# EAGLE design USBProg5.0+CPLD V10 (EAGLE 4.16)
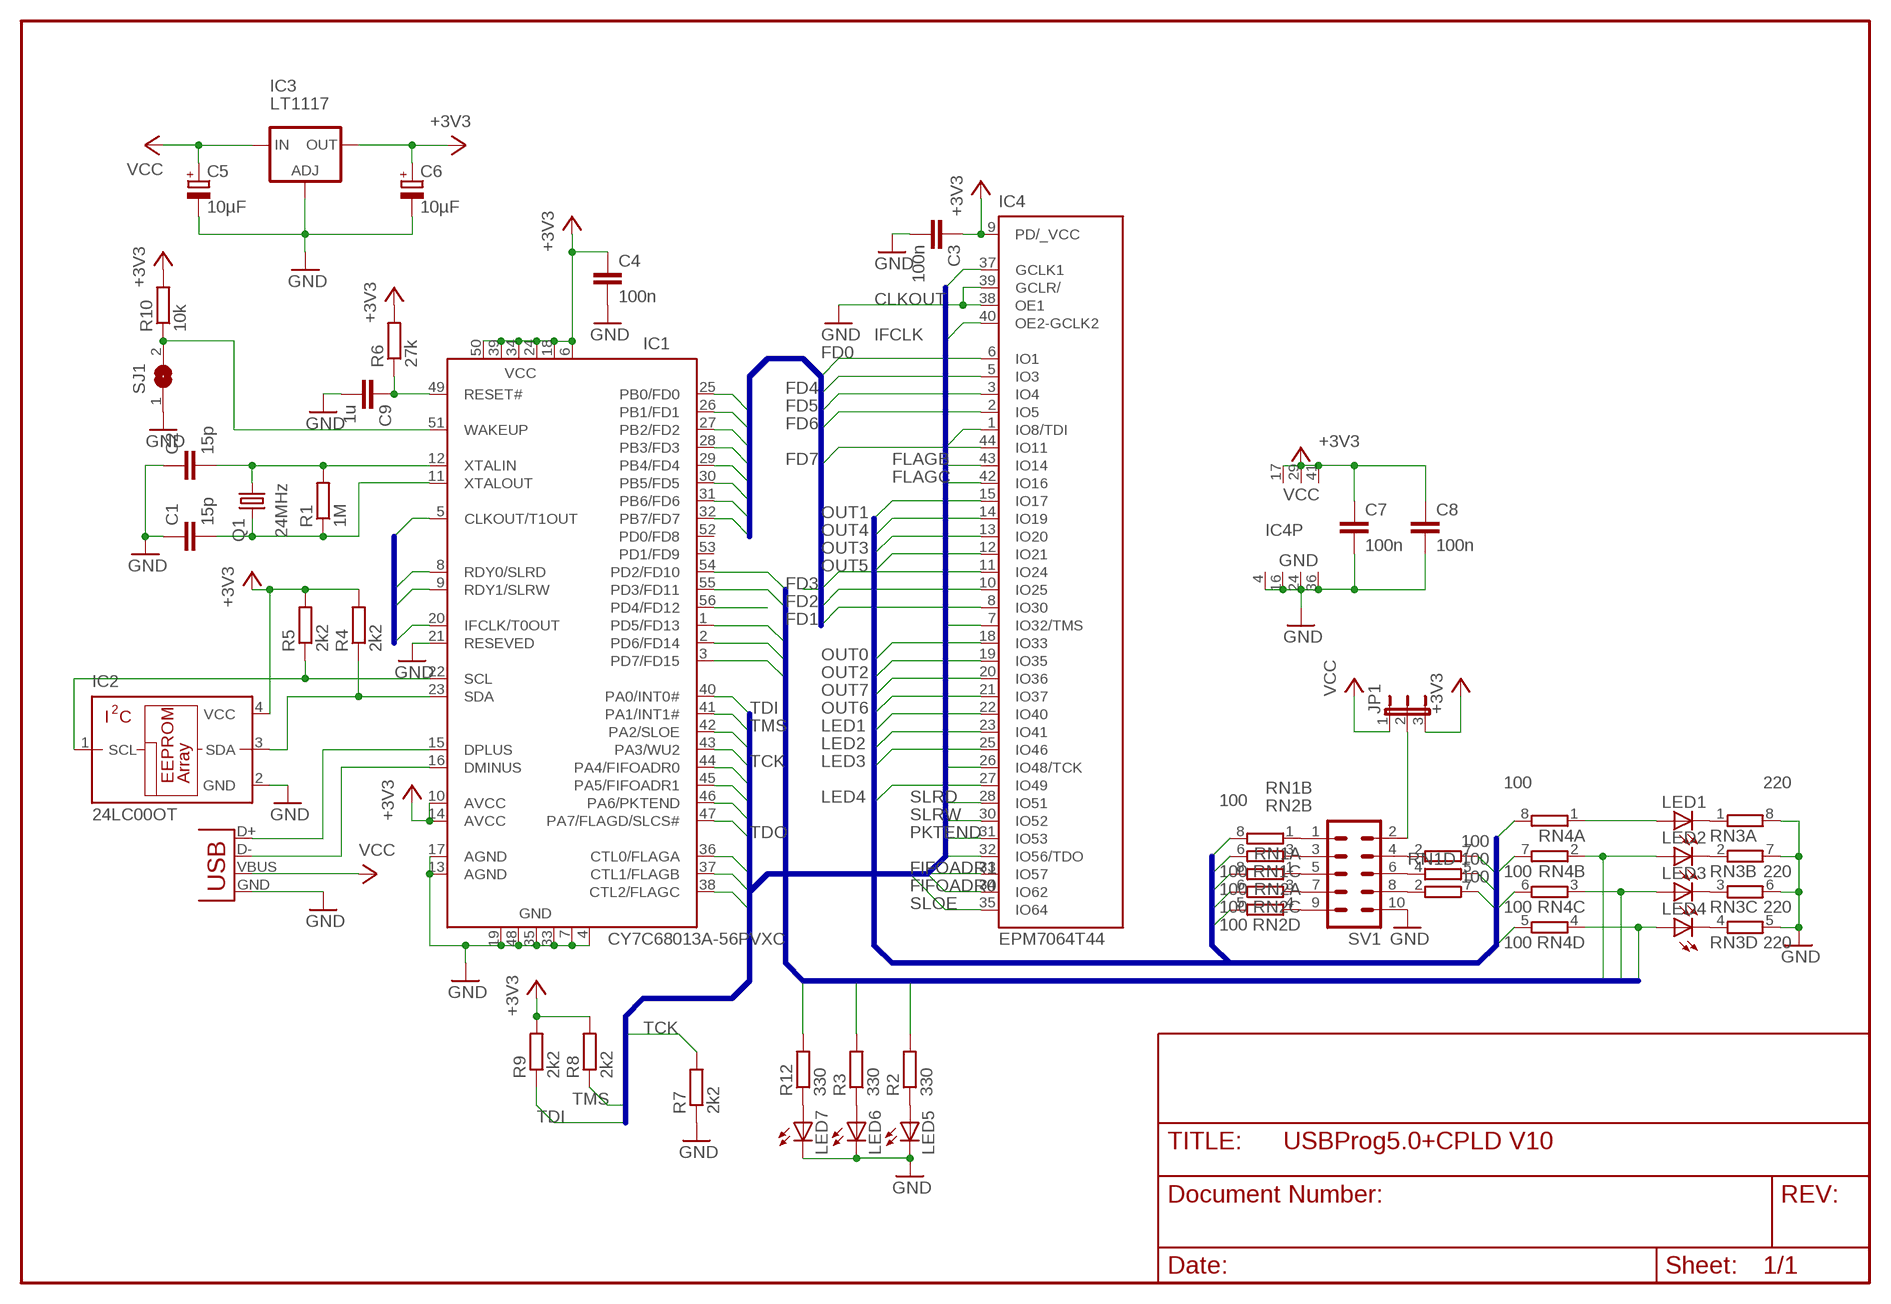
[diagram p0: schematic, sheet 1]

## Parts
C1  15p  RCL_C-EUC0603  [RCL_C0603]
C2  15p  RCL_C-EUC0603  [RCL_C0603]
C3  100n  RCL_C-EUC0603  [RCL_C0603]
C4  100n  RCL_C-EUC0603  [RCL_C0603]
C5  10µF  CPOL-EUSMCB  [SMC_B]
C6  10µF  CPOL-EUSMCB  [SMC_B]
C7  100n  RCL_C-EUC0603  [RCL_C0603]
C8  100n  RCL_C-EUC0603  [RCL_C0603]
C9  1u  RCL_C-EUC0805  [RCL_C0805]
IC1  CY7C68013A-56PVXC  [SSOP56]
IC2  24LC00OT  [SOT23-5L]
IC3  LT1117  LM317MBSTT3  [SOT223]
IC4  EPM7064T44  [TQFP44]
JP1  JP2E  [JP2]
LED1  LED_LEDCHIPLED_0603  [LED_CHIPLED_0603]
LED2  LED_LEDCHIPLED_0603  [LED_CHIPLED_0603]
LED3  LED_LEDCHIPLED_0603  [LED_CHIPLED_0603]
LED4  LED_LEDCHIPLED_0603  [LED_CHIPLED_0603]
LED5  LED_LEDCHIPLED_0603  [LED_CHIPLED_0603]
LED6  LED_LEDCHIPLED_0603  [LED_CHIPLED_0603]
LED7  LED_LEDCHIPLED_0603  [LED_CHIPLED_0603]
Q1  24MHz  CRYSTALSM49  [SM49]
R1  1M  RCL_R-EU_R0603  [RCL_R0603]
R2  330  RCL_R-EU_R0603  [RCL_R0603]
R3  330  RCL_R-EU_R0603  [RCL_R0603]
R4  2k2  RCL_R-EU_R0603  [RCL_R0603]
R5  2k2  RCL_R-EU_R0603  [RCL_R0603]
R6  27k  RCL_R-EU_R0603  [RCL_R0603]
R7  2k2  RCL_R-EU_R0603  [RCL_R0603]
R8  2k2  RCL_R-EU_R0603  [RCL_R0603]
R9  2k2  RCL_R-EU_R0603  [RCL_R0603]
R10  10k  RCL_R-EU_R0603  [RCL_R0603]
R12  330  RCL_R-EU_R0603  [RCL_R0603]
RN1  100  4R-N0402-ARV  [0402-ARV]
RN2  100  4R-N0402-ARV  [0402-ARV]
RN3  220  4R-N0402-ARV  [0402-ARV]
RN4  100  4R-N0402-ARV  [0402-ARV]
SJ1  SJ  [SJ]
SV1  ML10L  [ML10L]
X1  CON-USB_USB-B-H  [CON-USB_USB-B-H]

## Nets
+3V3: C3.1 C4.1 C6.+ C7.1 C8.1 IC1.6(VCC) IC1.10(AVCC) IC1.14(AVCC) IC1.18(VCC) IC1.24(VCC) IC1.34(VCC) IC1.39(VCC) IC1.50(VCC) IC2.4(VCC) IC3.4(OUT) IC4.9(PD/_VCC) IC4.17(VCC) IC4.29(VCC) IC4.41(VCC) JP1.3 R4.2 R5.2 R6.2 R8.2 R9.2 R10.2
CLKOUT: IC1.5(CLKOUT/T1OUT) IC4.37(GCLK1)
CPLD_LED1: LED1.A RN4.1
CPLD_LED2: IC1.55(PD3/FD11) LED2.A RN4.2
CPLD_LED3: IC1.56(PD4/FD12) LED3.A RN4.3
CPLD_LED4: IC1.54(PD2/FD10) LED4.A RN4.4
DMINUS: IC1.16(DMINUS) X1.D-
DPLUS: IC1.15(DPLUS) X1.D+
FD0: IC1.25(PB0/FD0) IC4.6(IO1)
FD1: IC1.26(PB1/FD1) IC4.8(IO30)
FD2: IC1.27(PB2/FD2) IC4.10(IO25)
FD3: IC1.28(PB3/FD3) IC4.11(IO24)
FD4: IC1.29(PB4/FD4) IC4.5(IO3)
FD5: IC1.30(PB5/FD5) IC4.3(IO4)
FD6: IC1.31(PB6/FD6) IC4.2(IO5)
FD7: IC1.32(PB7/FD7) IC4.44(IO11)
FIFOADR0: IC1.44(PA4/FIFOADR0) IC4.34(IO62)
FIFOADR1: IC1.45(PA5/FIFOADR1) IC4.33(IO57)
FLAGA: IC1.36(CTL0/FLAGA)
FLAGB: IC1.37(CTL1/FLAGB) IC4.43(IO14)
FLAGC: IC1.38(CTL2/FLAGC) IC4.42(IO16)
GND: C1.1 C2.1 C3.2 C4.2 C5.- C6.- C7.2 C8.2 C9.2 IC1.4(GND) IC1.7(GND) IC1.13(AGND) IC1.17(AGND) IC1.19(GND) IC1.21(RESEVED) IC1.33(GND) IC1.35(GND) IC1.48(GND) IC2.2(GND) IC3.1(ADJ) IC4.4(GND) IC4.16(GND) IC4.24(GND) IC4.36(GND) IC4.38(OE1) IC4.39(GCLR/) LED5.C LED6.C LED7.C R7.1 RN3.5 RN3.6 RN3.7 RN3.8 SJ1.1 SV1.10 X1.GND
IFCLK: IC1.20(IFCLK/T0OUT) IC4.40(OE2-GCLK2)
LED1: IC4.22(IO40) RN4.8
LED2: IC4.23(IO41) RN4.7
LED3: IC4.25(IO46) RN4.6
LED4: IC4.27(IO49) RN4.5
LED5: IC1.1(PD5/FD13) R2.2
LED6: IC1.2(PD6/FD14) R3.2
LED7: IC1.3(PD7/FD15) R12.2
N$1: C9.1 IC1.49(RESET#) R6.1
N$4: RN1.1 SV1.1
N$5: RN1.2 SV1.4
N$6: RN1.3 SV1.3
N$7: LED6.A R3.1
N$8: LED5.A R2.1
N$9: RN1.4 SV1.6
N$10: RN2.1 SV1.5
N$11: RN2.2 SV1.8
N$12: RN2.3 SV1.7
N$13: RN2.4 SV1.9
N$14: LED1.C RN3.1
N$15: LED2.C RN3.2
N$16: LED3.C RN3.3
N$17: LED4.C RN3.4
N$18: LED7.A R12.1
N$20: JP1.2 SV1.2
OUT0: IC4.18(IO33) RN2.8
OUT1: IC4.15(IO17) RN1.5
OUT2: IC4.19(IO35) RN2.7
OUT3: IC4.13(IO20) RN1.7
OUT4: IC4.14(IO19) RN1.6
OUT5: IC4.12(IO21) RN1.8
OUT6: IC4.21(IO37) RN2.5
OUT7: IC4.20(IO36) RN2.6
PKTEND: IC1.46(PA6/PKTEND) IC4.31(IO53)
SCL: IC1.22(SCL) IC2.1(SCL) R5.1
SDA: IC1.23(SDA) IC2.3(SDA) R4.1
SLOE: IC1.42(PA2/SLOE) IC4.35(IO64)
SLRD: IC1.8(RDY0/SLRD) IC4.28(IO51)
SLRW: IC1.9(RDY1/SLRW) IC4.30(IO52)
TCK: IC1.43(PA3/WU2) IC4.26(IO48/TCK) R7.2
TDI: IC1.40(PA0/INT0#) IC4.1(IO8/TDI) R9.1
TDO: IC1.47(PA7/FLAGD/SLCS#) IC4.32(IO56/TDO)
TMS: IC1.41(PA1/INT1#) IC4.7(IO32/TMS) R8.1
VCC: C5.+ IC3.3(IN) JP1.1 X1.VBUS
WAKEUP: IC1.51(WAKEUP) R10.1 SJ1.2
XTALIN: C2.2 IC1.12(XTALIN) Q1.1 R1.2
XTALOUT: C1.2 IC1.11(XTALOUT) Q1.2 R1.1
Unconnected: IC1.52(PD0/FD8) IC1.53(PD1/FD9)

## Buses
FD[0..7]
FIFOADR[0..1],FLAGA,FLAGB,FLAGC,PKTEND,SLRD,SLRW,SLOE,CLKOUT,IFCLK,TDI,TDO,TMS,TCK
OUT[0..7],LED[1..4]
LED[5..7],CPLD_LED[2..4]

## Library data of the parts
C1-C4 C7-C9 = usbprog_v3:RCL_C-EU: CAPACITOR, European symbol
C5 C6 = rcl:CPOL-EU: POLARIZED CAPACITOR, European symbol
IC1 = cypress:CY7C6801*A-56: EZ-USB FX2LP (TM) USB Microcontroller Source: http://www.cypress.com .. cy7c68013a_5.pdf
IC2 = microchip:24*00: Serial EEPROM 128 bit, I2C (AA = 1.8 V/LC = 2.5 V/C = 5.0 V)
IC3 = v-reg:LM317?*: 500 mA Adjustable Output Positive Voltage Regulator Source: http://www.onsemi.co.jp .. LM317M-D.PDF
IC4 = altera:EPM7064: EPM7064 MAX 7000 family
JP1 = jumper:JP2E: JUMPER
LED1-LED7 = usbprog_v3:LED_LED: LED
Q1 = crystal:CRYSTAL: CRYSTAL
R1-R10 R12 = usbprog_v3:RCL_R-EU_: RESISTOR, European symbol
RN1-RN4 = resistor-dil:4R-N: Array Chip Resistor Source: RS Component / Phycomp
SJ1 = jumper:SJ: SMD solder JUMPER
SV1 = con-harting-ml:ML10: HARTING
X1 = usbprog_v3:CON-USB_USB: USB Connectors

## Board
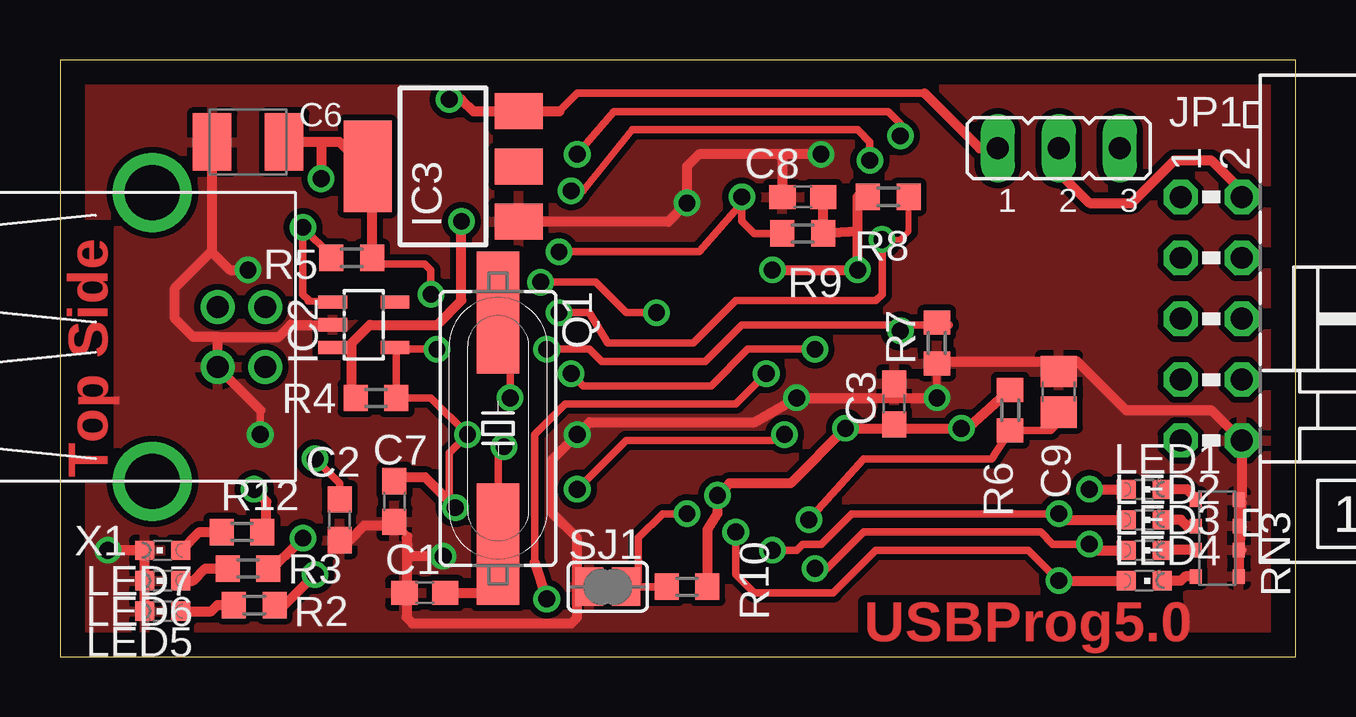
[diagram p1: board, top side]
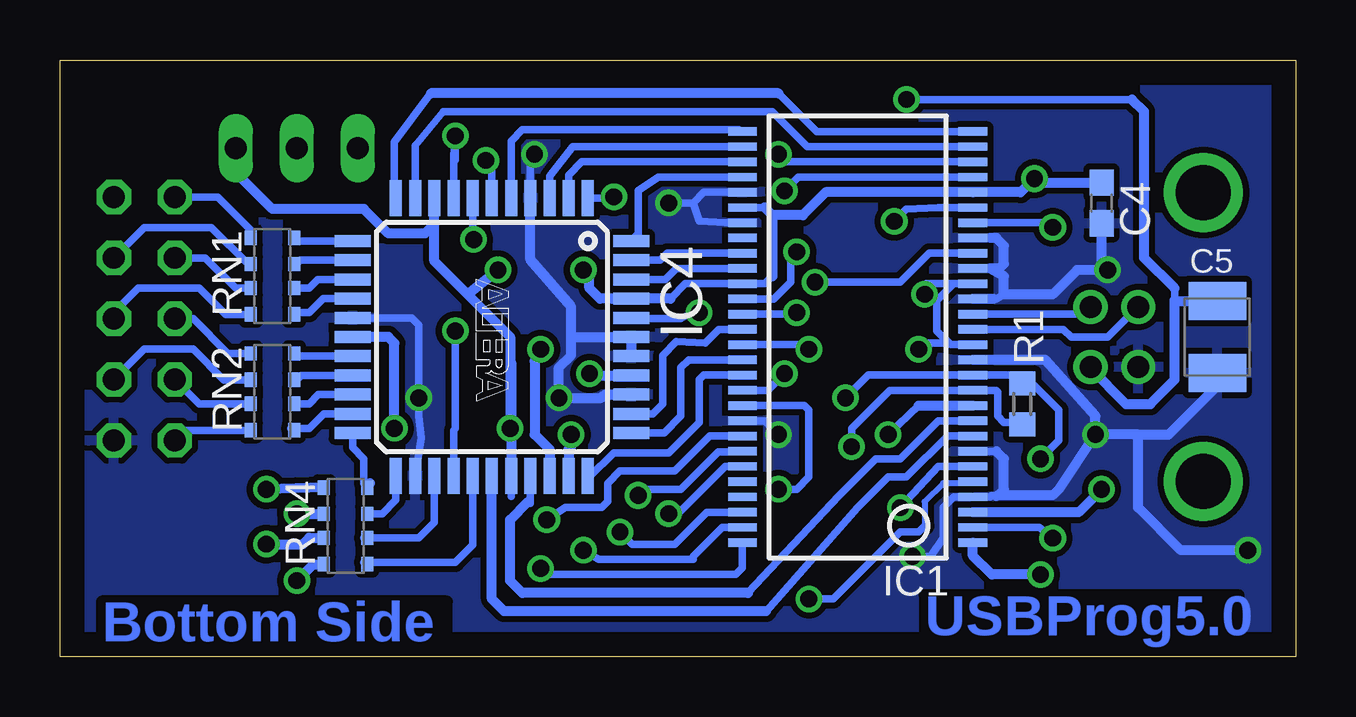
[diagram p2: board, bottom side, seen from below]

Size 51.49 x 24.88 mm. Coordinates in mm from the lower left corner, seen from the top.
Outline: 0,0 51.49,0 51.49,24.88 0,24.88 0,0
Copper layers (1*16): Top 0.035mm / dielectric 1.5mm / Bottom 0.035mm
Design rules "Bilex DRU": minimum track width 10mil, minimum drill 24mil, track to track 10mil, track to pad 10mil, pad to pad 10mil, via to via 10mil, smd to smd 10mil, copper to edge 40mil, drill to drill 8mil, minimum pad ring 10mil, minimum via ring 8mil, stop-mask expansion 4mil, vias tented up to drill 0mil, thermal gap 10mil

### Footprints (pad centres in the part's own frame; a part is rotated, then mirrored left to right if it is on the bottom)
RCL_C0603 = smd 1.1 x 1: 1 -0.85,0; 2 0.85,0
SMC_B = smd 1.6 x 2.4: + -1.5,0; - 1.5,0
RCL_C0805 = smd 1.3 x 1.5: 1 -0.85,0; 2 0.85,0
SSOP56 = smd 0.35 x 1.2: 1 -8.572,-4.8; 2 -7.938,-4.8; 3 -7.303,-4.8; 4 -6.668,-4.8; 5 -6.032,-4.8; 6 -5.397,-4.8; 7 -4.763,-4.8; 8 -4.128,-4.8; 9 -3.493,-4.8; 10 -2.857,-4.8; 11 -2.223,-4.8; 12 -1.587,-4.8; 13 -0.953,-4.8; 14 -0.318,-4.8; 15 0.318,-4.8; 16 0.953,-4.8; 17 1.587,-4.8; 18 2.223,-4.8; 19 2.857,-4.8; 20 3.493,-4.8; 21 4.128,-4.8; 22 4.763,-4.8; 23 5.397,-4.8; 24 6.032,-4.8; 25 6.668,-4.8; 26 7.303,-4.8; 27 7.938,-4.8; 28 8.572,-4.8; 29 8.572,4.8; 30 7.938,4.8; 31 7.303,4.8; 32 6.668,4.8; 33 6.032,4.8; 34 5.397,4.8; 35 4.763,4.8; 36 4.128,4.8; 37 3.493,4.8; 38 2.857,4.8; 39 2.223,4.8; 40 1.587,4.8; 41 0.953,4.8; 42 0.318,4.8; 43 -0.318,4.8; 44 -0.953,4.8; 45 -1.587,4.8; 46 -2.223,4.8; 47 -2.857,4.8; 48 -3.493,4.8; 49 -4.128,4.8; 50 -4.763,4.8; 51 -5.397,4.8; 52 -6.032,4.8; 53 -6.668,4.8; 54 -7.303,4.8; 55 -7.938,4.8; 56 -8.572,4.8
SOT23-5L = smd 0.55 x 1.2: 1 -0.95,-1.3; 2 0,-1.3; 3 0.95,-1.3; 4 0.95,1.3; 5 -0.95,1.3
SOT223 = smd 1.5 x 2: 1 -2.3,-3.15; 2 0,-3.15; 3 2.3,-3.15 | smd 3.8 x 2: 4 0,3.15
TQFP44 = smd 1.5 x 0.5: 1 -5.8,4; 2 -5.8,3.2; 3 -5.8,2.4; 4 -5.8,1.6; 5 -5.8,0.8; 6 -5.8,0; 7 -5.8,-0.8; 8 -5.8,-1.6; 9 -5.8,-2.4; 10 -5.8,-3.2; 11 -5.8,-4; 23 5.8,-4; 24 5.8,-3.2; 25 5.8,-2.4; 26 5.8,-1.6; 27 5.8,-0.8; 28 5.8,0; 29 5.8,0.8; 30 5.8,1.6; 31 5.8,2.4; 32 5.8,3.2; 33 5.8,4 | smd 0.5 x 1.5: 12 -4,-5.8; 13 -3.2,-5.8; 14 -2.4,-5.8; 15 -1.6,-5.8; 16 -0.8,-5.8; 17 0,-5.8; 18 0.8,-5.8; 19 1.6,-5.8; 20 2.4,-5.8; 21 3.2,-5.8; 22 4,-5.8; 34 4,5.8; 35 3.2,5.8; 36 2.4,5.8; 37 1.6,5.8; 38 0.8,5.8; 39 0,5.8; 40 -0.8,5.8; 41 -1.6,5.8; 42 -2.4,5.8; 43 -3.2,5.8; 44 -4,5.8
JP2 = drill 0.914 long: 1 -2.54,0; 2 0,0; 3 2.54,0
LED_CHIPLED_0603 = smd 0.8 x 0.8: A 0,-0.75; C 0,0.75
SM49 = smd 5.08 x 1.778: 1 -4.826,0; 2 4.826,0
RCL_R0603 = smd 1 x 1.1: 1 -0.85,0; 2 0.85,0
0402-ARV = smd 0.6 x 0.5: 1 -1.6,-0.9; 2 -0.5,-0.9; 3 0.5,-0.9; 4 1.6,-0.9; 5 1.6,0.9; 6 0.5,0.9; 7 -0.5,0.9; 8 -1.6,0.9
SJ = smd 1.168 x 1.6: 1 -0.762,0; 2 0.762,0
ML10L = drill 0.914 octagon: 1 -5.08,-1.27; 2 -5.08,1.27; 3 -2.54,-1.27; 4 -2.54,1.27; 5 0,-1.27; 6 0,1.27; 7 2.54,-1.27; 8 2.54,1.27; 9 5.08,-1.27; 10 5.08,1.27
CON-USB_USB-B-H = drill 0.914 round: D+ 0,1.25; D- 1.981,1.25; GND 0,-1.25; VBUS 1.981,-1.25 | drill 2.286 round: P$1 -2.718,-6.02; P$2 -2.718,6.02

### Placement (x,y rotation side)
C1  15.2,2.66 0 top
C2  11.65,5.71 90 top
C3  34.76,10.54 90 top
C4  8.09,18.92 270 bottom
C5  3.26,13.33 270 bottom
C6  7.84,21.46 180 top
C7  13.93,6.47 270 top
C8  30.95,19.17 180 top
C9  41.62,11.04 90 top
IC1  18.25,13.33 90 bottom
IC2  12.66,13.84 270 top
IC3  15.96,20.44 90 top
IC4  33.49,13.33 270 bottom
JP1  41.62,21.2 0 top
LED1  45.17,6.98 270 top
LED2  45.17,5.71 270 top
LED3  45.17,4.44 270 top
LED4  45.17,3.17 270 top
LED5  4.28,1.9 90 top
LED6  4.28,3.17 90 top
LED7  4.28,4.44 90 top
Q1  18.25,9.52 270 top
R1  11.39,10.54 90 bottom
R2  8.09,2.15 0 top
R3  7.84,3.68 0 top
R4  13.17,10.79 0 top
R5  12.15,16.63 0 top
R6  39.59,10.28 90 top
R7  36.54,13.08 90 top
R8  34.51,19.17 180 top
R9  30.95,17.65 0 top
R10  26.12,2.92 0 top
R12  7.58,5.2 0 top
RN1  42.63,15.87 270 bottom
RN2  42.63,11.04 270 bottom
RN3  48.22,4.95 270 top
RN4  39.59,5.46 270 bottom
SJ1  22.82,2.92 0 top
SV1  47.97,14.09 270 top
X1  6.57,13.33 0 top

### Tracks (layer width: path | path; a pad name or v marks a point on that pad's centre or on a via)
+3V3  (via drill 0.7)
  Top 0.254: C7.1 14.1,7.49 | C3.1 34.67,9.69 34.51,9.52
  Top 0.305: IC3.4 12.66,20.44 | v37.55,9.52 37.81,9.52 37.9,9.61 | 33.24,19.17 R8.2 | 16.22,6.47 16.22,8.5 v16.98,9.27 15.46,10.79 R4.2 14.02,12.73 13.93,12.82 13.96,12.85 IC2.4 14.03,12.82 v15.71,12.82 | v15.46,15.11 15.46,16.12 15.2,16.38 13.17,16.38 13,16.54 R5.2
  Top 0.406: v37.55,9.52 34.51,9.52 v32.73,9.52 30.44,7.23 27.9,7.23 v27.39,6.73 27.39,5.96 26.97,5.29 R10.2 | v29.68,16.12 v33.24,16.12 33.24,17.74 | 10.88,21.46 C6.+ | 10.88,21.46 11.65,21.46 12.66,20.44 | 37.9,9.61 R6.2 | 33.24,17.74 R9.2 31.97,17.65 31.8,17.81 C8.1 | 33.24,17.74 33.24,19.17 | 14.1,7.49 15.2,7.49 16.22,6.47 v16.47,6.22 | 10.88,21.46 v10.88,19.93 | IC3.4 12.81,20.59 12.92,20.7 13,20.61 R5.2
  Bottom 0.305: 26.05,14.93 25.43,15.55 IC1.39 22.12,15.55 21.81,15.87 | IC1.50 23.05,8.53 24.07,8.53 25.62,6.98 27.14,6.98 v27.39,6.73 | IC4.29 32.69,6.69 | 22.12,18.73 IC1.34 | IC4.9 35.89,18.04 | v32.73,9.52 32.69,12.28 | IC4.17 39.33,13.33 | IC4.41 28.49,14.93 | 14.76,10.47 15.71,10.47 v16.98,9.27 | IC1.6 14.88,7.93 v16.47,6.22 | IC1.14 14.38,13.01 14.44,13.08 | 14.44,13.08 14.95,13.58 14.95,14.85 14.25,15.55 IC1.18 15.39,15.55 v15.46,15.11 | v15.71,12.82 15.46,13.08 14.44,13.08
  Bottom 0.406: 26.05,14.93 IC4.41 | 21.81,18.41 21.81,15.87 | 21.81,18.41 22.12,18.73 | 21.81,18.41 20.54,18.41 19.58,19.36 IC1.24 11.45,19.36 v10.88,19.93 10.72,19.77 C4.1 | 35.89,18.04 36.28,17.65 37.81,17.65 38.82,18.66 42.63,18.66 44.16,20.19 JP1.3 | 32.69,12.28 IC4.29 | v37.55,9.52 37.55,13.08 37.81,13.33 IC4.17 | IC4.9 35.89,16.49 34.51,15.11 | 34.51,15.11 32.73,13.33 v32.73,9.52 | 28.49,14.93 28.99,14.93 29.43,15.36 29.43,15.87 v29.68,16.12 | v33.24,16.12 34.51,15.11 | 15.71,10.47 IC1.10
CLKOUT  (via drill 0.7)
  Top 0.305: v29.43,11.81 28.16,10.54 21.04,10.54 19.77,9.27 19.77,3.93
  Top 0.406: v20.28,2.41 19.77,3.93
  Bottom 0.254: IC1.5 13.51,7.23 14.69,7.23 15.46,6.47 15.46,5.46
  Bottom 0.305: v29.43,11.81 29.1,11.73 | 15.46,5.46 15.71,5.2 16.47,5.2 19.27,2.41 v20.28,2.41
  Bottom 0.406: 29.1,11.73 IC4.37
CPLD_LED1  (via drill 0.7)
  Top 0.406: v42.89,6.98 LED1.A
  Bottom 0.406: RN4.1 v42.89,6.98
CPLD_LED2  (via drill 0.7)
  Top 0.305: v29.68,4.44 30.7,4.44 30.95,4.69 31.71,4.69 32.98,5.96 v41.62,5.96
  Top 0.406: v41.62,5.96 41.87,5.71 LED2.A
  Bottom 0.305: IC1.55 23.9,5.39 25.11,4.19 25.11,4.06 29.05,4.06 v29.68,4.44
  Bottom 0.406: v41.62,5.96 RN4.2
CPLD_LED3  (via drill 0.7)
  Top 0.305: v31.46,3.68 31.97,3.68 33.49,5.2 40.86,5.2 41.36,4.69 v42.89,4.69
  Top 0.406: v42.89,4.69 43.14,4.44 LED3.A
  Bottom 0.305: IC1.56 23.05,3.7 23.33,3.42 31.2,3.42 v31.46,3.68
  Bottom 0.406: RN4.3 41.1,4.96 41.36,4.69 v42.89,4.69
CPLD_LED4  (via drill 0.7)
  Top 0.305: v28.16,5.2 28.16,3.42 28.92,2.66 32.22,2.66 34,4.44 40.35,4.44 v41.62,3.17
  Top 0.406: v41.62,3.17 LED4.A
  Bottom 0.305: IC1.54 24.54,6.03 25.87,4.69 27.65,4.69 v28.16,5.2
  Bottom 0.406: RN4.4 40.93,3.86 v41.62,3.17
DMINUS
  Bottom 0.305: X1.D- 8.58,14.58 8.6,14.6 8.91,14.28 IC1.16
DPLUS
  Bottom 0.305: IC1.15 9.68,13.65 9.36,13.33 7.84,13.33 6.57,14.6 X1.D+
FD0  (via drill 0.7)
  Top 0.305: v21.3,19.43 21.81,19.43 23.84,21.97 33.24,21.97 33.74,21.46 v33.74,20.7
  Bottom 0.305: IC1.25 20.73,20 v21.3,19.43 | v33.74,20.7 33.49,20.44 IC4.6
FD1  (via drill 0.7)
  Top 0.305: v21.55,20.95 23.08,22.73 34.51,22.73 35.01,22.22 v35.01,21.71
  Bottom 0.305: IC1.26 21.23,20.63 v21.55,20.95 | 35.01,20.7 v35.01,21.71 35.09,20.87 IC4.8
FD2
  Bottom 0.305: IC1.27 20.34,21.27 21.81,22.73 35.52,22.73 36.69,21.31 IC4.10
FD3
  Bottom 0.305: IC1.28 19.96,21.9 21.55,23.49 | IC4.11 37.51,19.13 37.55,19.17 37.55,21.46 36.03,23.49
  Bottom 0.406: 21.55,23.49 36.03,23.49
FD4
  Bottom 0.305: IC4.5 32.69,21.5 32.22,21.97 23.2,21.97 23.14,21.9 IC1.29
FD5
  Bottom 0.305: IC1.30 30.12,21.27 31.09,20.05 IC4.3
FD6
  Bottom 0.305: IC1.31 29.74,20.63 30.29,20.09 IC4.2
FD7
  Bottom 0.305: IC1.32 26.57,20 27.39,19.43 27.39,17.65 27.69,17.35 IC4.44
FIFOADR0
  Bottom 0.305: IC1.44 25.3,12.38 25.62,12.06 25.62,10.03 26.31,9.33 IC4.34
FIFOADR1
  Bottom 0.305: IC1.45 24.66,11.74 24.85,11.55 24.85,9.77 26.12,8.5 28.41,8.5 29.43,7.49 29.47,7.53 IC4.33
FLAGB
  Bottom 0.305: IC1.37 26.19,16.82 26.48,16.53 IC4.43
FLAGC
  Bottom 0.305: IC1.38 25.81,16.19 26.26,15.73 IC4.42
GND  (via drill 0.7)
  Top 0.254: 14.61,4.19 14.52,5.03 C7.2 | 34.76,10.79 C3.2
  Top 0.305: 6.57,12.06 X1.GND | 6.31,16.89 6.34,16.91 | v8.34,9.27 8.34,10.28 | v36.54,10.79 36.54,12.31 | 36.79,11.97 R7.1 | 14.44,2.66 C1.1 | 12.07,4.86 C2.1 | C7.2 13.93,5.46 | 14.52,5.03 14.44,4.95
  Top 0.406: 29.93,20.95 26.63,20.95 26.12,20.44 v26.12,18.92 25.35,18.14 IC3.1 | v31.71,20.95 29.93,20.95 | v36.54,10.79 34.76,10.79 v30.7,10.79 28.92,9.77 22.06,9.77 v21.55,9.27 20.54,8.25 20.54,5.96 21.55,4.95 21.55,2.92 | 41.62,12.31 36.54,12.31 36.79,11.97 | 41.62,12.31 42.38,12.31 44.41,10.28 47.97,10.28 SV1.10 49.24,6.66 RN3.8 49.24,6.47 RN3.7 49.24,5.46 RN3.6 49.23,4.45 49.24,4.44 49.12,4.32 RN3.5 | 6.34,16.91 C6.- | 6.57,13.33 5.55,13.33 4.79,14.09 4.79,15.36 6.31,16.89 7.07,16.12 v7.84,16.12 | IC2.2 9.61,13.84 9.11,13.33 6.57,13.33 | 6.57,13.33 6.57,12.06 8.34,10.28 | 21.55,2.92 21.55,1.65 21.3,1.39 14.69,1.39 14.44,1.65 14.44,2.66 14.44,4.95 | v15.96,4.19 14.61,4.19 | 12.07,4.86 12.66,5.46 13.93,5.46 | 21.55,2.92 SJ1.1 | C8.2 30.1,20.78 29.93,20.95 | LED5.C LED6.C 3.52,3.17 LED6.C LED7.C 3.52,4.44 LED7.C v1.99,4.44 | 41.62,12.31 C9.2
  Bottom 0.254: IC1.7 13.51,8.5 | 2.76,11.81 C5.-
  Bottom 0.305: IC1.35 23.77,18.09 24.85,18.16 25.11,18.92 | IC1.33 24.66,19.36 25.11,18.92 | IC4.4 31.89,20.77 v31.71,20.95 | v26.12,18.92 25.11,18.92 | IC1.48 22.12,9.84 v21.55,9.27 | IC4.24 36.44,9.11 36.54,10.03 v36.54,10.79 36.54,13.84 36.83,14.13 IC4.16 | 12.47,8.57 IC1.7 | v15.96,4.19 15.2,4.19 14.69,4.95 14.69,6.22 14.25,6.66 IC1.4 12.73,6.66 12.66,6.73 12.41,6.73 | 12.73,17.46 IC1.21 | 12.6,16.19 IC1.19 12.73,16.19 | 12.15,15.11 12.47,14.92 12.6,14.92
  Bottom 0.356: 12.15,6.98 12.41,6.73 12.47,6.66
  Bottom 0.406: IC4.36 28.78,10.93 28.92,10.79 v30.7,10.79 30.7,12.06 30.19,12.57 30.19,13.33 | IC4.4 31.89,16.56 30.19,14.6 30.19,13.33 | 12.15,6.98 12.15,8.25 12.47,8.57 | IC1.13 10.44,12.38 8.34,10.03 v8.34,9.27 | 12.73,17.46 12.47,17.46 12.15,17.14 12.15,16.38 12.41,16.12 12.47,16.19 12.6,16.19 | 12.73,16.19 12.15,15.87 12.15,15.11 10.12,15.11 9.11,16.12 v7.84,16.12 8.09,16.38 C4.2 | 12.6,14.92 IC1.17 | 2.76,11.81 5.3,9.27 6.57,9.27 | 6.57,9.27 v8.34,9.27 | 27.65,13.33 IC4.39 | IC4.38 27.69,13.29 27.65,13.33 | 30.19,13.33 27.65,13.33 | v8.34,9.27 9.87,6.98 10.12,6.73 12.41,6.73 | v1.99,4.44 4.79,4.44 6.57,6.22 6.57,9.27
  pour Top: -0.29,25.27 52.03,25.27 52.03,-0.89 -0.8,-0.89 -0.8,25.27
  pour Bottom (isolate 0.254): -0.8,26.03 52.54,26.03 52.54,-1.66 -1.05,-1.66 -1.05,26.28 -0.8,26.28 -0.8,25.78
IFCLK  (via drill 0.7)
  Top 0.305: v20.03,15.62 22.31,15.62 23.58,14.35 v24.85,14.35
  Bottom 0.305: IC1.20 15.26,16.82 16.47,15.62 v20.03,15.62 | v24.85,14.35 25.11,14.35 25.62,14.09 27.65,14.09 IC4.40
LED1
  Bottom 0.305: IC4.22 39.29,8.72 38.82,8.25 38.82,7.23 38.69,7.1
  Bottom 0.406: RN4.8 38.57,7.23 38.69,7.1
LED2
  Bottom 0.305: IC4.23 37.49,6.54 38.06,5.96 38.57,5.96 38.58,5.96 RN4.7
LED3
  Bottom 0.305: IC4.25 35.89,5.6 36.54,4.95 38.57,4.95 38.82,4.95 38.82,4.96
  Bottom 0.406: 38.57,4.95 RN4.6
LED4
  Bottom 0.305: IC4.27 34.29,4.66 35.01,3.93 38.57,3.93 38.82,3.93 38.75,3.86
  Bottom 0.406: 38.57,3.93 RN4.5
LED5  (via drill 0.7)
  Top 0.406: R2.2 9.36,2.15 v10.63,3.42
  Bottom 0.406: v10.63,3.42 12.66,3.42 13.45,4.21 IC1.1
LED6  (via drill 0.7)
  Top 0.305: 10.12,4.69 v10.12,4.95
  Top 0.406: R3.2 8.85,3.68 9.87,4.69 10.12,4.69
  Bottom 0.305: IC1.2 10.69,5.39 v10.12,4.95
LED7  (via drill 0.7)
  Top 0.305: 8.47,5.33 8.6,5.2 R12.2
  Top 0.406: v8.09,6.98 8.6,6.47 8.6,5.46 8.47,5.33 8.34,5.2
  Bottom 0.406: IC1.3 9.04,6.03 v8.09,6.98
N$1  (via drill 0.7)
  Top 0.305: v31.2,5.71 33.49,8.25 38.82,8.25 R6.1 | R6.1 39.59,9.27 | C9.1 41.62,9.77 41.28,9.43 R6.1
  Bottom 0.305: IC1.49 24.41,9.2 25.87,7.74 28.16,7.74 28.66,7.23 28.66,6.47 28.92,6.22 30.44,6.22 v31.2,5.71
N$4
  Bottom 0.305: RN1.1 43.53,17.79 44.92,19.17 SV1.1
N$5
  Bottom 0.305: RN1.2 43.64,16.37 45.17,17.9 47.97,17.9 SV1.4
N$6
  Bottom 0.305: RN1.3 44.17,15.37 45.43,16.63 SV1.3
N$7
  Top 0.406: LED6.A 5.55,3.17 6.06,3.68 R3.1
N$8
  Top 0.406: R2.1 6.57,2.15 6.31,1.9 LED5.A
N$9
  Bottom 0.305: RN1.4 44.59,14.27 45.68,15.36 48.22,15.36 49.24,14.35 SV1.6
N$10
  Bottom 0.305: RN2.1 44.49,12.64 45.94,14.09 SV1.5
N$11
  Bottom 0.305: RN2.2 44.66,11.54 45.94,12.82 47.97,12.82 SV1.8
N$12
  Bottom 0.305: RN2.3 45.69,10.54 SV1.7
N$13
  Bottom 0.305: RN2.4 46.27,9.44 SV1.9
N$14
  Top 0.406: RN3.1 47.32,6.61 46.95,6.98 LED1.C
N$15
  Top 0.406: RN3.2 46.96,5.45 46.7,5.71 LED2.C
N$16
  Top 0.406: LED3.C 46.19,4.44 46.2,4.45 RN3.3
N$17
  Top 0.406: RN3.4 46.88,3.35 46.7,3.17 LED4.C
N$18
  Top 0.406: LED7.A 5.8,5.2 R12.1
N$20
  Top 0.305: 49.24,19.43 SV1.2
  Top 0.406: 49.24,19.43 47.97,20.7 46.44,20.7 44.67,18.92 42.89,18.92 41.62,20.19 JP1.2
OUT0
  Bottom 0.305: RN2.8 41.69,12.64 41.58,12.53 IC4.18
OUT1
  Bottom 0.305: IC4.15 40.53,14.93 41.11,14.35 41.62,14.35 41.69,14.27 RN1.5
OUT2
  Bottom 0.305: RN2.7 41.63,11.54 41.44,11.73 IC4.19
OUT3
  Bottom 0.305: RN1.7 41.63,16.37 41.47,16.53 IC4.13
OUT4
  Bottom 0.305: IC4.14 40.74,15.73 41.11,15.36 41.62,15.36 41.63,15.37 RN1.6
OUT5
  Bottom 0.305: RN1.8 41.69,17.47 41.55,17.33 IC4.12
OUT6
  Bottom 0.305: IC4.21 40.5,10.13 41.11,9.52 41.87,9.52 41.8,9.44 RN2.5
OUT7
  Bottom 0.305: IC4.20 40.72,10.93 41.11,10.54 41.62,10.54 41.63,10.54 RN2.6
PKTEND  (via drill 0.7)
  Top 0.305: v21.3,11.81 21.81,11.3 27.14,11.3 28.66,12.82 v31.46,12.82
  Bottom 0.305: IC1.46 22,11.11 v21.3,11.81
  Bottom 0.406: v31.46,12.82 31.71,12.31 31.71,9.27 31.09,8.64 IC4.31
SCL  (via drill 0.7)
  Top 0.305: IC2.1 10.35,14.82 10.38,14.85 10.12,15.11 v10.12,17.9 11.3,16.72 R5.1
  Bottom 0.305: IC1.22 10.31,18.09 v10.12,17.9
SDA  (via drill 0.7)
  Top 0.254: IC2.3 11.36,12.85 11.39,12.82 11.9,12.82
  Top 0.305: R4.1 12.15,10.79 | 12.15,13.08 11.9,12.82
  Top 0.406: v16.73,18.16 16.73,14.85 15.71,13.84 12.92,13.84 12.15,13.08 12.15,10.79
  Bottom 0.305: IC1.23 14.88,18.73 16.22,18.66 v16.73,18.16
SLOE
  Bottom 0.305: IC1.42 24.03,13.65 24.6,13.08 25.81,13.14 26.38,12.57 26.38,10.54 26.78,10.13 IC4.35
SLRD
  Bottom 0.305: IC1.8 14.5,9.2 16.22,7.49 16.98,7.49 18.25,6.22 22.06,1.9
  Bottom 0.406: IC4.28 33.49,2.41 32.98,1.9 22.06,1.9
SLRW
  Bottom 0.305: 22.82,2.66 19.01,6.73 17.49,8.25 16.47,8.25 14.88,9.84 IC1.9 | 31.89,6.47 IC4.30 | 31.89,6.47 31.89,6.4 | 31.97,6.47 31.89,6.47
  Bottom 0.406: 22.82,2.66 32.22,2.66 32.73,3.17 32.73,5.71 31.97,6.47
TCK  (via drill 0.7)
  Top 0.305: v20.28,12.82 22.06,12.82 22.57,12.31 26.89,12.31 28.41,13.84 34.76,13.84 v35.01,13.58 35.27,13.84 37.05,13.84 R7.2
  Bottom 0.305: IC1.43 20.6,13.01 v20.28,12.82 | v35.01,13.58 35.01,9.52 35.09,9.44 IC4.26
TDI  (via drill 0.7)
  Top 0.305: v20.79,16.89 26.63,16.89 28.41,18.92 v28.41,19.17 28.41,18.16 28.92,17.65 R9.1
  Bottom 0.305: IC4.1 28.45,19.13 v28.41,19.17 | v20.79,16.89 21.04,16.63 21.04,15.62 21.74,14.92 IC1.40
TDO  (via drill 0.7)
  Top 0.305: v21.55,6.98 23.58,9.01 29.68,9.01 v30.19,9.27
  Bottom 0.305: IC1.47 20.47,10.47 20.28,10.28 20.28,7.49 20.79,6.98 v21.55,6.98
  Bottom 0.406: v30.19,9.27 30.19,8.76 30.29,8.66 IC4.32
TMS  (via drill 0.7)
  Top 0.254: R8.1 35.36,17.74 35.01,17.39 v34.25,17.39
  Top 0.305: v34.25,17.39 34.25,15.11 34,14.85 28.16,14.85 26.38,13.08 22.82,13.08 22.06,14.35 v20.79,14.35
  Bottom 0.305: IC4.7 34.29,17.43 v34.25,17.39 | IC1.41 20.85,14.28 v20.79,14.35
VCC  (via drill 0.7)
  Top 0.305: 20.8,22.74 21.55,23.49 36.03,23.49 | v16.22,23.24 16.73,23.24
  Top 0.406: 20.8,22.74 IC3.3 17.22,22.74 16.73,23.24 | 36.03,23.49 38.32,21.2 JP1.1
  Bottom 0.254: 5.04,14.85 5.02,14.83
  Bottom 0.305: 6.82,23.24 v16.22,23.24 | 5.04,14.85 5.04,15.36 | 8.55,12.01 X1.VBUS
  Bottom 0.406: 6.82,23.24 6.31,22.73 6.31,16.63 5.04,15.36 | 5.04,14.85 5.04,11.55 6.06,10.54 7.07,10.54 8.55,12.01 | 5.02,14.83 C5.+
WAKEUP  (via drill 0.7)
  Top 0.305: 23.84,2.92 24.6,2.92 | v26.12,5.96 25.11,5.96 24.09,4.95 24.09,3.17 23.84,2.92 | SJ1.2 23.84,2.92 | 23.84,2.92 R10.1
  Bottom 0.305: IC1.51 23.77,7.93 25.74,5.96 v26.12,5.96
XTALIN  (via drill 0.7)
  Top 0.305: v18.76,10.79 18.76,12.31 18.25,12.57 Q1.1 | C2.2 11.65,7.23 v10.63,8.25
  Bottom 0.305: v10.63,8.25 9.87,9.01 9.87,10.28 11.14,11.55 11.3,11.39 R1.2 11.39,11.3 11.84,11.74 IC1.12 17.8,11.74 v18.76,10.79
XTALOUT  (via drill 0.7)
  Top 0.305: v18.5,8.76 18.25,8.5 Q1.2 18.25,2.92 18,2.66
  Top 0.406: C1.2 18,2.66
  Bottom 0.305: R1.1 11.39,9.77 12.15,9.77 12.41,10.03 12.41,11.04 12.47,11.11 IC1.11 16.92,11.11 18.5,9.52 v18.5,8.76

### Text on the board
Top: Top Side | USBProg5.0
Bottom: USBProg5.0 | Bottom Side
